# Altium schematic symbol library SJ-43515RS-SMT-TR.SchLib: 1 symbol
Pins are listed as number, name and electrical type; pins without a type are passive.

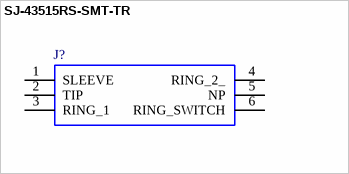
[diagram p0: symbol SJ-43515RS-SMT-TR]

## SJ-43515RS-SMT-TR
designator J?
4 conductor 3.5 mm Surface Mount Audio Jack w/ Ring Switch; Manufacturer_Name: CUI Devices; Geometry.Height: 5.1mm
footprint SJ43515RSSMTTR
pins: 1 SLEEVE, 2 TIP, 3 RING_1, 4 RING_2_, 5 NP, 6 RING_SWITCH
